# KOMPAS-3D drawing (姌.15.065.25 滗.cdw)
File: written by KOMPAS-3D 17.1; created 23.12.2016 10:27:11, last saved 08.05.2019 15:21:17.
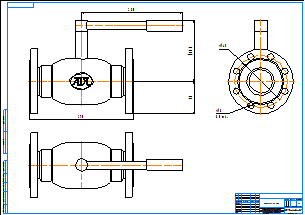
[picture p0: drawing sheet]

Sheet 1: A1, landscape

Title block, sheet 1: name: КШ.15.065.25 фф; material: Внимание! Данный продукт является объектом авторского права ООО «Торговый Дом АДЛ». / Запрещается изменение, копирование, распространение / (в том числе путем копирования на другие сайты и ресурсы в Интернете) / или любое иное использование информации и объектов без предварительного / согласия правообладателя (ООО «Торговый Дом АДЛ»).; sheets: 1; organisation: ООО "Торговый дом АДЛ"; sheet format: A1; stored path: C:\Users\tra\Desktop\2д чертежи\Шаровые краны БИВАЛ\КШ_Бивал_серия_14_15\KOMPAS_2D\КШ.15.065.25 фф.cdw

Views: Вид 1, Проекционный вид 2, Проекционный вид 3
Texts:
  Klimkovich
  ADL
Dimensions and other numbers on the sheet: 290; 280; 168,8; 90; 145; 18; 8 Отв.; 1:1; 1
